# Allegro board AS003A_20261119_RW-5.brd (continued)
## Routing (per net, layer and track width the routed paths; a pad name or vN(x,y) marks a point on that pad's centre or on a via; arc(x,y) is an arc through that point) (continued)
S1_PCIE_TX_P[1]: length 124.5
  L09_DIG w0.079: v3(330.45,278.13) 330.45,277.65 330.56,277.55 338.05,277.55 340.98,274.62 354.17,274.62 356.3,272.49 356.3,259.79 353.74,257.23 319.79,257.23 294.62,232.07 294.62,227.94 294.83,227.73 294.83,227.71
  L09_DIG w0.102: v1(294.43,223.83) 294.83,224.23 294.83,227.71
  BOTTOM w0.117: C259.2 R128.1 arc(330,277.76) 330.26,277.94 v3(330.45,278.13)
S1_PCIE_TX_P[2]: length 124.5
  L09_DIG w0.079: 292.43,227.71 292.43,227.73 292.64,227.94 292.64,233.3 318.47,259.13 342.27,259.13 344.29,261.15 344.29,267.35 342.93,268.71 340.51,268.71 335.39,273.84 326.31,273.84 323.52,276.63 323.52,281.6 322.02,283.11 319.76,283.11 318.56,281.91 318.56,278.18 317.35,276.97 315.31,276.97 315.21,276.87 v3(315.21,276.48)
  L09_DIG w0.102: v1(292.83,223.83) 292.43,224.23 292.43,227.71
  BOTTOM w0.117: C260.2 R132.1 arc(314.76,276.84) 315.02,276.67 v3(315.21,276.48)
S1_PCIE_TX_P[3]: length 124.5
  L09_DIG w0.079: v3(299.97,276.48) 299.97,276.88 300.05,276.96 307.08,276.96 309.69,274.34 311.28,274.34 313.89,271.73 313.89,258.12 312.91,257.14 282.98,257.14 282.04,256.2 282.04,254.08 282.84,253.29 303.53,253.29 305,251.82 305,248.55 291.04,234.59 291.04,227.94 290.83,227.73 290.83,227.71
  L09_DIG w0.102: 290.83,227.71 290.83,224.23 v1(291.23,223.83)
  BOTTOM w0.117: C264.2 R136.1 arc(299.52,276.84) 299.78,276.67 v3(299.97,276.48)
S1_PCIE_TX_P[4]: length 124.5
  L09_DIG w0.079: v3(284.73,276.48) 284.73,276.89 284.81,276.97 289,276.97 289.44,276.53 289.44,267.34 279.11,257.02 254.39,257.02 253.21,255.84 253.21,252.49 254.31,251.39 288.49,251.39 289.44,250.45 289.44,227.94 289.23,227.73 289.23,227.71
  L09_DIG w0.102: v1(289.63,223.83) 289.23,224.23 289.23,227.71
  BOTTOM w0.117: C268.2 R140.1 arc(284.28,276.84) 284.54,276.67 v3(284.73,276.48)
S1_PCIE_TX_P[5]: length 124.5
  L09_DIG w0.079: 287.63,227.71 287.63,227.73 287.84,227.94 287.84,229.77 283.53,234.07 283.53,236.81 277.09,243.26 277.09,245.43 275.42,247.11 243.75,247.11 242.19,248.67 242.19,256.93 244.02,258.76 270.54,258.76 273.33,261.55 273.33,275.69 272.06,276.96 269.57,276.96 269.49,276.88 v3(269.49,276.48)
  L09_DIG w0.102: v1(288.03,223.83) 287.63,224.23 287.63,227.71
  BOTTOM w0.117: C275.2 R144.1 arc(269.04,276.84) 269.3,276.67 v3(269.49,276.48)
S1_PCIE_TX_P[6]: length 124.5
  L09_DIG w0.079: v3(254.25,276.48) 254.25,276.89 254.33,276.97 255.68,276.97 257.89,274.76 257.89,265.2 255.24,262.55 235.76,262.55 231.22,258.01 231.22,249.58 236.82,243.99 273.32,243.99 281.45,235.86 281.45,234.09 286.24,229.3 286.24,227.94 286.03,227.73 286.03,227.71
  L09_DIG w0.102: v1(286.43,223.83) 286.03,224.23 286.03,227.71
  BOTTOM w0.117: v3(254.25,276.48) 254.06,276.67 arc(253.8,276.84) R148.1 C279.2
S1_PCIE_TX_P[7]: length 124.5
  L09_DIG w0.079: v3(239.01,276.48) 239.01,276.88 239.09,276.96 240.94,276.96 243.21,274.7 243.21,265.34 241.9,264.03 227.95,264.03 225.45,261.52 225.45,243.2 226.35,242.3 270.84,242.3 284.64,228.5 284.64,227.94 284.43,227.73 284.43,227.71
  L09_DIG w0.102: 284.43,227.71 284.43,224.23 v1(284.83,223.83)
  BOTTOM w0.117: v3(239.01,276.48) 238.82,276.67 arc(238.56,276.84) R152.1 C280.2
S1_PHY0_RESEXT: length 9.1
  BOTTOM w0.508: v1(298.7,232.83) R109.1
  vias: v1(291.23,221.43)
S1_PHY0_RESEXT_1: length 3
  BOTTOM w0.508: R109.2 K3.3
S1_PHY0_SYS_CLK1R_N:
  vias: v1(330.33,236.21)
S1_PHY0_SYS_CLK1R_P:
  vias: v1(330.33,220.99)
S1_PHY0_SYS_CLK2_N:
  vias: v1(336.16,228.85) v1(337.75,228.85)
S1_PHY0_SYS_CLK2_P:
  vias: v1(336.16,227.58) v1(337.75,227.88)
S1_PHY0_SYS_CLK3_N:
  vias: v1(331.34,235.2) v1(335.16,230.12) v1(335.16,228.85)
S1_PHY0_SYS_CLK3_P:
  vias: v1(331.34,222) v1(335.16,227.58) v1(335.16,226.31)
S1_PHY0_SYS_CLK_N:
  vias: v1(292.83,222.23)
S1_PHY0_SYS_CLK_P:
  vias: v1(292.83,221.43)
S1_PHY1_RESEXT: length 9.1
  BOTTOM w0.508: v1(287.65,232.83) R111.1
  vias: v1(288.03,221.43)
S1_PHY1_RESEXT_1: length 3
  BOTTOM w0.508: R111.2 K4.3
S1_PHY1_SYS_CLK1R_N:
  vias: v1(330.33,253.48)
S1_PHY1_SYS_CLK1R_P:
  vias: v1(330.33,238.26)
S1_PHY1_SYS_CLK2_N:
  vias: v1(336.16,246.13) v1(337.75,246.13)
S1_PHY1_SYS_CLK2_P:
  vias: v1(336.16,244.86) v1(337.75,245.15)
S1_PHY1_SYS_CLK3_N:
  vias: v1(331.34,252.48) v1(335.16,247.4) v1(335.16,246.13)
S1_PHY1_SYS_CLK3_P:
  vias: v1(331.34,239.27) v1(335.16,244.86) v1(335.16,243.59)
S1_PHY1_SYS_CLK_N:
  vias: v1(289.63,222.23)
S1_PHY1_SYS_CLK_P:
  vias: v1(289.63,221.43)
S1_UHC4_1F:
  vias: v1(221.49,237.87) v1(221.49,235.58) v1(221.49,233.3) v1(221.49,231.01)
S1_UHC4_1GS:
  vias: v1(221.49,242.44)
S1_UHC4_1S:
  vias: v1(221.49,240.16)
S1_UHC4_2F:
  vias: v1(380.37,252.73) v1(380.37,250.44) v1(380.37,248.16) v1(380.37,245.87)
S1_UHC4_2GS:
  vias: v1(380.37,257.3)
S1_UHC4_2S:
  vias: v1(380.37,255.02)
S1_UHC4_3F:
  vias: v1(221.62,194.44) v1(221.62,192.15) v1(221.62,189.87) v1(221.62,187.58)
S1_UHC4_3GS:
  vias: v1(221.62,199.01)
S1_UHC4_3S:
  vias: v1(221.62,196.72)
S1_VCC18V_VQPS:
  vias: v1(294.43,207.83)
S1_XIN:
  vias: v1(290.43,203.03)
UDBGND:
  vias: v1(169.98,297.69) v1(169.98,294.89) v1(170.17,137.92) v1(170.45,135.64) v1(190.97,135.07) v1(191.06,137.92) v1(206.67,297.56) v1(206.96,295.27) v1(320.21,132.84) v1(320.49,130.55) v1(344.73,133.6) v1(344.8,130.75) v1(401.5,133.6) v1(401.5,130.56) v1(421.89,277.57) v1(422.27,283.63) v1(425.45,283.23) v1(425.96,277.57)
UT1_UP5V: length 45
  TOP w0.508: RV8.1 296.16,180.12 K7.1 ; RV11.1 352.65,227.08 K10.1 ; LRB3.1 172.72,190.5 KS3.3 ; KS1.1 161.17,161.88 LRB1.1 ; K5.1 256.06,208.53 RV6.1 ; K8.1 328.52,196.85 RV9.1 ; RV13.1 369.92,238.76 K12.1 ; LRB2.1 178.32,161.88 KS2.1 ; K4.1 284.86,249.4 RV5.1 ; LRB4.1 172.72,181.61 KS4.3 ; K6.1 328.52,214.12 RV7.1 ; K9.1 283.97,180.12 RV10.1 ; RV4.1 295.91,249.4 K3.1 ; RV12.1 352.65,244.35 K11.1
  vias: v1(171.87,137.92) v1(172.95,135.64) v1(208.37,297.56) v1(209.46,295.27) v1(321.94,248.07) v1(321.94,230.8) v1(321.91,132.84) v1(322.99,130.55) v1(422.27,285.33) v1(425.45,285.73)
UT1_URW00: length 7.7
  TOP w0.508: LDB3.2 162.56,190.5 KS3.1
UT1_URW01: length 7.7
  TOP w0.508: LDB4.2 162.56,181.61 KS4.1
UT1_URW02: length 3.8
  TOP w0.508: KS2.9 182.36,161.88 LDB2.2
UT1_URW03: length 3.8
  TOP w0.508: LDB1.2 165.21,161.88 KS1.9
N19435169: length 19.6
  BOTTOM w0.508: C287.1 390.66,230.38 391.41,230.38
  BOTTOM w0.762: 391.41,230.38 C285.1 394.55,230.38 395.06,229.87 395.06,228.09 ; R15.1 R153.1 ; R153.1 395.06,225.81 395.06,228.09 ; R153.1 R162.1 ; R16.1 R162.1 ; R162.1 395.06,228.09
N19572213:
  vias: v1(321.94,229.95) v1(321.94,227.83)
N19572313:
  vias: v1(321.94,247.23) v1(321.94,245.1)
N19572428:
  vias: v1(339.16,229.83) v1(340.74,229.35)
N19572509:
  vias: v1(339.16,247.1) v1(340.74,246.63)
N19574075: length 1.2
  TOP w0.508: RV4.2 DV4.1
N19574343: length 1.2
  TOP w0.508: RV5.2 DV5.1
N19575291: length 1.2
  TOP w0.508: RV8.2 DV8.1
N19575453: length 3.5
  BOTTOM w0.508: K7.4 296.17,188.07 OSC1.3
N19585514: length 1.2
  TOP w0.508: RV10.2 DV10.1
N19585599: length 6.7
  BOTTOM w0.508: OSC1.1 287.52,185.53 K9.6 K9.3
N19585804: length 2.6
  BOTTOM w0.508: R116.1 K9.4
N19747460: length 2
  BOTTOM w0.762: R21.1 BD16.2
N19747478: length 8.4
  BOTTOM w0.508: 391.41,252.22 390.66,252.22 C290.1
  BOTTOM w0.762: R22.1 BD15.2 395.06,251.71 394.55,252.22 C288.1 391.41,252.22
N19756616: length 1.2
  TOP w0.508: RV11.2 DV11.1
N19756896:
  vias: v1(342.26,228.35)
N19756906:
  vias: v1(342.26,229.35)
N19757084: length 1.2
  TOP w0.508: RV12.2 DV12.1
N19757142:
  vias: v1(342.26,245.63)
N19757144:
  vias: v1(342.26,246.63)
N19788638: length 1.2
  TOP w0.508: RV9.2 DV9.1
N20007134: length 1.2
  TOP w0.508: RV6.2 DV6.1
N20007610: length 1.2
  TOP w0.508: RV7.2 DV7.1
N20116208:
  vias: v1(350.39,233.75) v1(352.14,233.75)
N20116223:
  vias: v1(348.49,233.75)
N20117866:
  vias: v1(356.23,240.83) v1(358.07,240.86)
N20117958: length 1.2
  TOP w0.508: RV13.2 DV13.1
N20118012:
  vias: v1(359.54,239.78)
N20118014:
  vias: v1(359.54,240.78)
N20118429:
  vias: v1(339.78,234.26)
N20125555:
  vias: v1(339.78,235.53)
N20125558:
  vias: v1(339.78,239.09)
N20322895: length 3.7
  BOTTOM w0.762: KS2.4 KS2-4.1
N20322897: length 1.5
  TOP w0.508: LDB1.1 LRB1.2
N20322901: length 3.6
  BOTTOM w0.762: KS2.3 KS2-3.1
N20322902: length 3.7
  BOTTOM w0.762: KS2.6 KS2-6.1
N20322905: length 3.6
  BOTTOM w0.762: KS2.7 KS2-7.1
N20322907: length 1.5
  TOP w0.508: LDB2.1 LRB2.2
N20322911: length 3.7
  BOTTOM w0.762: KS1.4 KS1-4.1
N20322913: length 3.6
  BOTTOM w0.762: KS1.3 KS1-3.1
N20322914: length 3.7
  BOTTOM w0.762: KS1.6 KS1-6.1
N20322915: length 3.6
  BOTTOM w0.762: KS1.7 KS1-7.1
N20322919: length 3.6
  BOTTOM w0.762: KS1.2 KS1-2.1
N20322920: length 3.6
  BOTTOM w0.762: KS1.8 KS1-8.1
N20322921: length 3.6
  BOTTOM w0.762: KS2.2 KS2-2.1
N20322922: length 3.6
  BOTTOM w0.762: KS2.8 KS2-8.1
N20322925: length 1.5
  TOP w0.508: LRB3.2 LDB3.1
N20322930: length 1.5
  TOP w0.508: LRB4.2 LDB4.1
N20322942: length 3.8
  TOP w0.762: KS4.4 180.85,179.07 KS4-4.1
N20322943: length 3.8
  TOP w0.762: KS4.5 180.85,176.53 KS4-5.1
N20322944: length 3.6
  TOP w0.762: KS4.8 KS4-8.1
N20322953: length 3.6
  TOP w0.762: KS3.8 KS3-8.1
N20322954: length 3.8
  TOP w0.762: KS3.4 180.85,187.96 KS3-4.1
N20322955: length 3.8
  TOP w0.762: KS3-5.1 180.85,185.42 KS3.5
N20403651:
  vias: v1(55.49,220.9) v1(55.48,219.88)
N20403655: length 9.7
  BOTTOM w0.117: OSC5.1 58.98,218.17 R259.1 61.98,220.26 64.06,220.26 K13.6
N20403856: length 4.6
  TOP w0.254: K13.8 DV14.2 S1_K13_CBIT.1
N20403862: length 1.3
  TOP w0.254: DV14.1 RV14.2
N20403864: length 48.1
  TOP w0.508: K13.1 71.34,215.18 RV14.1 73.08,213.53 ; v1(41.28,220.4) 39.75,218.87 RV16.1
  L03_DIG w1.016: v1(41.28,220.4) 42.42,221.53 45.21,221.53 45.85,222.17 54.74,222.17 55.63,223.06 v1(65.66,223.06) 70.61,223.06 72.52,221.15 72.52,217.22 K13.1
  BOTTOM w0.508: K15.1 v1(41.28,220.4)
N20403912: length 3.1
  BOTTOM w0.117: K13.4 62.21,216.71 R261.1
N20403914: length 3.1
  BOTTOM w0.117: R261.2 62.21,217.72 K13.5
N20408352: length 7.7
  TOP w0.254: DV16.2 39.75,214.55 v1(41.28,213.01) 40,211.74 S1_K15_CBIT.1
  BOTTOM w0.254: K15.9 v1(41.28,213.01)
N20408383: length 1.2
  TOP w0.254: DV16.1 RV16.2
N20409909:
  vias: v1(55.49,203.75) v1(55.48,202.74)
N20409913: length 9.7
  BOTTOM w0.117: OSC6.1 58.98,201.02 R260.1 61.98,203.12 64.06,203.12 K14.6
N20410006: length 4.6
  TOP w0.254: K14.8 DV15.2 S1_K14_CBIT.1
N20410012: length 1.3
  TOP w0.254: DV15.1 RV15.2
N20410014: length 48.1
  TOP w0.508: v1(41.28,203.26) 39.75,201.72 RV17.1 ; 73.08,196.39 RV15.1 71.34,198.04 K14.1
  L03_DIG w1.016: K14.1 72.52,200.08 72.52,204.01 70.61,205.91 55.63,205.91 54.74,205.02 45.85,205.02 45.21,204.39 42.42,204.39 v1(41.28,203.26)
  BOTTOM w0.508: K16.1 v1(41.28,203.26)
N20410038: length 3.1
  BOTTOM w0.117: R262.1 62.21,199.57 K14.4
N20410040: length 3.1
  BOTTOM w0.117: K14.5 62.21,200.57 R262.2
N20410345: length 3.4
  TOP w0.508: S1_DB_OSC5_PWR.1 v1(58.76,221.41) v1(58.76,219.75)
N20410600: length 4.9
  TOP w0.254: v1(41.28,195.87) 39.75,197.4 DV17.2
  BOTTOM w0.254: K16.9 v1(41.28,195.87)
N20410614: length 1.2
  TOP w0.254: DV17.1 RV17.2
N20412222: length 1.7
  TOP w0.762: v1(58.76,202.61) v1(58.76,204.26)
N20412556: length 2.3
  BOTTOM w0.117: K15.6 v1(51.43,213.02)
N20412563: length 2.3
  BOTTOM w0.117: K15.4 v1(51.43,220.39)
N20412610: length 2.3
  BOTTOM w0.117: K16.6 v1(51.43,195.88)
N20412613: length 2.3
  BOTTOM w0.117: K16.4 v1(51.43,203.24)
N20439603:
  vias: v1(55.49,162.94) v1(55.48,161.93)
N20439607: length 9.7
  BOTTOM w0.117: OSC7.1 58.98,160.21 R273.1 61.98,162.31 64.06,162.31 K17.6
N20439693: length 4.6
  TOP w0.254: K17.8 DV18.2 S1_K17_CBIT.1
N20439699: length 1.3
  TOP w0.254: DV18.1 RV18.2
N20439701: length 48.1
  TOP w0.508: K17.1 71.34,157.23 RV18.1 73.08,155.57 ; RV19.1 39.75,160.91 v1(41.28,162.44)
  L03_DIG w1.016: K17.1 72.52,159.27 72.52,163.19 70.61,165.1 55.63,165.1 54.74,164.21 45.85,164.21 45.21,163.58 42.42,163.58 v1(41.28,162.44)
  BOTTOM w0.508: K18.1 v1(41.28,162.44)
N20439733: length 3.1
  BOTTOM w0.117: K17.4 62.21,158.76 R274.1
N20439735: length 3.1
  BOTTOM w0.117: K17.5 62.21,159.76 R274.2
N20439828: length 4.9
  TOP w0.254: v1(41.28,155.06) 39.75,156.59 DV19.2
  BOTTOM w0.254: K18.9 v1(41.28,155.06)
N20439842: length 1.2
  TOP w0.254: DV19.1 RV19.2
N20439950:
  vias: v1(55.49,180.09) v1(55.48,179.07)
N20439954: length 9.7
  BOTTOM w0.117: K19.6 64.06,179.45 61.98,179.45 R281.1 58.98,177.36 OSC8.1
N20440050: length 4.6
  TOP w0.254: S1_K19_CBIT.1 DV20.2 K19.8
N20440056: length 1.3
  TOP w0.254: DV20.1 RV20.2
N20440058: length 48.1
  TOP w0.508: RV21.1 39.75,178.06 v1(41.28,179.59) ; 73.08,172.72 RV20.1 71.34,174.37 K19.1
  L03_DIG w1.016: v1(41.28,179.59) 42.42,180.72 45.21,180.72 45.85,181.36 54.74,181.36 55.63,182.25 70.61,182.25 72.52,180.34 72.52,176.41 K19.1
  BOTTOM w0.508: K20.1 v1(41.28,179.59)
N20440074: length 3.1
  BOTTOM w0.117: R282.1 62.21,175.9 K19.4
N20440076: length 3.1
  BOTTOM w0.117: R282.2 62.21,176.9 K19.5
N20440163: length 1.7
  TOP w0.762: v1(58.76,161.8) v1(58.76,163.45)
N20440184: length 4.9
  TOP w0.254: DV21.2 39.75,173.73 v1(41.28,172.2)
  BOTTOM w0.254: K20.9 v1(41.28,172.2)
N20440198: length 1.2
  TOP w0.254: DV21.1 RV21.2
N20440326: length 1.7
  TOP w0.762: v1(58.76,178.94) v1(58.76,180.59)
N20440363: length 2.3
  BOTTOM w0.117: K18.6 v1(51.43,155.07)
N20440379: length 2.3
  BOTTOM w0.117: K18.4 v1(51.43,162.43)
N20440395: length 2.3
  BOTTOM w0.117: K20.6 v1(51.43,172.21)
N20440397: length 2.3
  BOTTOM w0.117: K20.4 v1(51.43,179.58)

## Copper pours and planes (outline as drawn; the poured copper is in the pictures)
DGND on L34_DIG (solid shape): 304.47,199.71 304.47,197.53 305.73,196.28 305.75,196.18 305.68,196.11 305.62,196.08 305.53,196.09 305.48,196.18 305.48,196.38 304.33,197.53 304.33,199.66 303.16,200.83 303.15,200.88 303.19,200.91 303.27,200.91
DGND on L34_DIG (solid shape): 316.84,206.07 316.86,205.96 316.77,205.9 316.66,205.9 312.01,210.55 310.42,210.55 310.34,210.59 310.33,210.68 310.35,210.81 310.33,210.94 310.35,211.03 310.43,211.07 311.84,211.07
DGND on L34_DIG (solid shape): 316.85,209.27 316.85,208.43 316.79,208.34 316.68,208.36 312.67,212.38 310.44,212.38 310.36,212.42 310.34,212.5 310.34,212.65 310.31,212.78 310.31,212.88 310.4,212.93 313.2,212.93
DGND on L34_DIG (solid shape): 271.92,221.8 272.01,221.77 272.05,221.72 272.05,220.75 272.01,220.66 271.92,220.65 271.32,220.12 272.09,219.89 272.13,219.91 272.16,219.89 272.49,219.56 272.52,219.45 272.42,219.39 271.68,219.39 271.21,219.86 271.21,221.46 271.25,221.54 271.34,221.55 271.63,221.57 271.85,221.75
DGND on L34_DIG (solid shape): 267.6,209.81 267.63,209.86 267.69,209.85 269.2,208.34 276.71,208.34 276.8,208.27 276.78,208.16 276.07,207.45 275.68,207.45 275.6,207.49 275.59,207.59 275.17,208.23 274.75,207.59 274.74,207.49 274.66,207.45 272.28,207.45 272.2,207.49 272.19,207.59 271.77,208.23 271.35,207.59 271.34,207.49 271.26,207.45 269.9,207.45 267.6,209.75
DGND on L34_DIG (solid shape): outline of 231 points within 256.01,222.42 272.51,227.99
DGND on L34_DIG (solid shape): 290.31,177.44 290.37,177.53 290.48,177.51 292.1,175.89 292.1,172.91 312.43,152.57 312.43,113.48 315.89,110.02 315.89,99.5 315.82,99.4 315.7,99.45 314.12,99.06 315.7,98.67 315.82,98.72 315.89,98.62 315.89,89.34 315.82,89.24 315.7,89.29 314.12,88.9 315.7,88.51 315.82,88.56 315.89,88.46 315.89,79.18 315.82,79.08 315.7,79.13 314.12,78.74 315.7,78.35 315.82,78.4 315.89,78.3 315.89,69.02 315.82,68.92 315.7,68.97 314.12,68.58 315.7,68.19 315.82,68.24 315.89,68.14 315.89,58.86 315.82,58.76 315.7,58.81 314.12,58.42 315.7,58.03 315.82,58.08 315.89,57.98 315.89,48.7 315.82,48.6 315.7,48.65 314.12,48.26 315.7,47.87 315.82,47.92 315.89,47.82 315.89,38.54 315.82,38.44 315.7,38.49 315.28,38.88 314.7,38.9 314.68,38.89 314,39.57 314,109.16 312.16,111 312.16,151.93 290.31,173.78 290.31,175.38 290.37,175.47 290.49,175.45 291.29,175.75 290.49,176.05 290.37,176.02 290.31,176.12
DGND on L34_DIG (solid shape): outline of 84 points within 319.75,38.59 409.78,212.05
DGND on L34_DIG (solid shape): outline of 650 points within 310.33,38.47 404.77,214.59
DGND on L34_DIG (solid shape): outline of 764 points within 295.16,97.06 323.36,192.8
DGND on L34_DIG (solid shape): outline of 844 points within 239.23,38.5 268.13,209.44
DGND on L34_DIG (solid shape): outline of 1276 points within 295.59,38.47 326.04,200.8
DGND on L02_DGND: 302.07,1.02 290.83,6.67 279.59,1.02 1.02,1.02 1.02,428.24 205.93,428.24 217.17,422.59 228.41,428.24 353.25,428.24 364.49,422.59 375.73,428.24 580.64,428.24 580.64,1.02 ; 1 cut-out
DGND on L03_DIG, L05_DIG, L07_DIG, L09_DIG, L30_DIG: 1.27,1.27 1.27,427.99 205.8,427.99 217.17,422.33 228.54,427.99 353.12,427.99 364.49,422.33 375.86,427.99 435.88,427.99 435.88,1.27 302.2,1.27 290.83,6.93 279.46,1.27
(no net) on BOTTOM: 254.28,149.15 254.28,152.35 253.67,152.96 244.53,152.96 243.81,152.25 243.81,149.15 243.97,149 254.13,149
(no net) on BOTTOM: 364.77,164.52 364.77,165.84 365.68,166.75 365.68,169.11 364.9,169.9 356.08,169.9 355.4,169.21 355.4,166.73 356.59,165.53 356.59,164.44 356.67,164.36 364.62,164.36
(no net) on BOTTOM: 55.24,160.15 55.24,163.58 55.63,163.96 57.53,163.96 57.53,161.16 57.28,160.91 56.9,160.91 56.77,160.78 56.77,159.89 55.5,159.89
(no net) on BOTTOM: 393.19,226.31 392.56,226.95 390.65,226.95 389.76,227.84 389.76,233.25 391.31,234.8 395.61,234.8 396.09,234.31 397.59,234.31 397.59,236.91 396.62,237.87 388.49,237.87 385.95,235.33 385.95,219.2 388.62,216.53 397.13,216.53 397.61,217.02 397.61,219.63 394.92,219.63 393.19,221.36
(no net) on BOTTOM: 323.37,149.15 323.37,150.47 324.28,151.38 324.28,153.75 323.49,154.53 314.68,154.53 313.99,153.85 313.99,151.36 315.19,150.16 315.19,149.07 315.26,149 323.21,149
(no net) on BOTTOM: 324.13,164.52 324.13,165.84 325.04,166.75 325.04,169.11 324.26,169.9 315.44,169.9 314.76,169.21 314.76,166.73 315.95,165.53 315.95,164.44 316.03,164.36 323.98,164.36
(no net) on BOTTOM: 55.24,177.29 55.24,180.72 55.63,181.1 57.53,181.1 57.53,178.31 57.28,178.05 56.9,178.05 56.77,177.93 56.77,177.04 55.5,177.04
(no net) on BOTTOM: 378.54,186.46 375.34,186.46 374.74,185.87 374.74,178.9 375.36,178.28 378.61,178.28 378.69,178.36 378.69,186.31
(no net) on BOTTOM: 55.24,218.1 55.24,221.53 55.63,221.91 57.53,221.91 57.53,219.12 57.28,218.87 56.9,218.87 56.77,218.74 56.77,217.85 55.5,217.85
(no net) on BOTTOM: 343.81,164.52 343.81,165.84 344.73,166.75 344.73,169.11 343.94,169.9 335.13,169.9 334.44,169.21 334.44,166.73 335.64,165.53 335.64,164.44 335.71,164.36 343.66,164.36
(no net) on BOTTOM: 289.84,149.15 289.84,153.26 288.57,154.53 282.68,154.53 281.66,153.52 281.66,149.07 281.74,149 289.69,149
(no net) on BOTTOM: 270.28,154.53 261.09,154.53 259.31,152.76 259.31,149.25 259.56,149 272.06,149 272.16,149.1 272.16,152.65
(no net) on BOTTOM: 306.35,149.15 306.35,150.47 307.26,151.38 307.26,153.75 306.48,154.53 297.66,154.53 296.98,153.85 296.98,151.36 298.17,150.16 298.17,149.07 298.25,149 306.2,149
(no net) on BOTTOM: 55.24,200.96 55.24,204.39 55.63,204.77 57.53,204.77 57.53,201.97 57.28,201.72 56.9,201.72 56.77,201.59 56.77,200.7 55.5,200.7
(no net) on BOTTOM: 375.59,194.79 378.61,194.79 378.69,194.87 378.69,200.66 378.66,200.69 375.39,200.69 374.98,200.28 374.98,195.4
(no net) on L02_DGND: 59.94,494.67 95,494.67 95.5,495.17 95.5,511.05 95,511.56 59.94,511.56 59.44,511.05 59.44,495.17
(no net) on L02_DGND: 60.58,476.76 95.63,476.76 96.14,477.27 96.14,493.14 95.63,493.65 60.58,493.65 60.07,493.14 60.07,477.27
(no net) on L32_DIG, L34_DIG: 1.27,1.27 1.27,427.99 205.8,427.99 217.17,422.33 228.54,427.99 353.12,427.99 364.49,422.33 375.86,427.99 435.88,427.99 435.88,1.27 302.2,1.27 290.83,6.93 279.46,1.27
S1_DPS1 on BOTTOM (solid shape): 307.26,153.75 307.26,151.38 306.35,150.47 306.35,149.15 306.2,149 298.25,149 298.17,149.07 298.17,150.16 296.98,151.36 296.98,153.85 297.66,154.53 306.48,154.53
S1_DPS3 on BOTTOM (solid shape): 378.69,186.31 378.69,178.36 378.61,178.28 375.36,178.28 374.74,178.9 374.74,185.87 375.34,186.46 378.54,186.46
S1_DPS4 on BOTTOM (solid shape): 325.04,169.11 325.04,166.75 324.13,165.84 324.13,164.52 323.98,164.36 316.03,164.36 315.95,164.44 315.95,165.53 314.76,166.73 314.76,169.21 315.44,169.9 324.26,169.9
S1_DPS5 on BOTTOM (solid shape): 289.84,153.26 289.84,149.15 289.69,149 281.74,149 281.66,149.07 281.66,153.52 282.68,154.53 288.57,154.53
S1_DPS7 on BOTTOM (solid shape): 324.28,153.75 324.28,151.38 323.37,150.47 323.37,149.15 323.21,149 315.26,149 315.19,149.07 315.19,150.16 313.99,151.36 313.99,153.85 314.68,154.53 323.49,154.53
S1_DPS9 on BOTTOM (solid shape): 365.68,169.11 365.68,166.75 364.77,165.84 364.77,164.52 364.62,164.36 356.67,164.36 356.59,164.44 356.59,165.53 355.4,166.73 355.4,169.21 356.08,169.9 364.9,169.9
S1_DPS10 on BOTTOM (solid shape): 344.73,169.11 344.73,166.75 343.81,165.84 343.81,164.52 343.66,164.36 335.71,164.36 335.64,164.44 335.64,165.53 334.44,166.73 334.44,169.21 335.13,169.9 343.94,169.9
S1_DPS11 on BOTTOM: 375.59,206.48 378.61,206.48 378.69,206.55 378.69,212.34 378.66,212.37 375.39,212.37 374.98,211.96 374.98,207.09
S1_DPS12 on BOTTOM: 375.59,164.82 378.61,164.82 378.69,164.9 378.69,170.69 378.66,170.71 375.39,170.71 374.98,170.31 374.98,165.43
S1_DPS17 on BOTTOM (solid shape): 397.59,236.91 397.59,234.31 396.09,234.31 395.61,234.8 391.31,234.8 389.76,233.25 389.76,227.84 390.65,226.95 392.56,226.95 393.19,226.31 393.19,221.36 394.92,219.63 397.61,219.63 397.61,217.02 397.13,216.53 388.62,216.53 385.95,219.2 385.95,234.85 386.92,234.85 386.92,234.79 386.93,234.73 386.94,234.68 386.97,234.62 387,234.57 387.03,234.53 387.08,234.49 387.13,234.45 387.18,234.43 387.23,234.41 387.29,234.39 387.35,234.39 387.41,234.39 387.47,234.41 387.52,234.43 387.57,234.45 387.62,234.49 387.67,234.53 387.7,234.57 387.73,234.62 387.76,234.68 387.77,234.73 387.78,234.79 387.78,234.85 387.77,234.91 387.76,234.97 387.73,235.02 387.7,235.07 387.67,235.12 387.62,235.16 387.57,235.19 387.52,235.22 387.47,235.24 387.41,235.25 387.35,235.26 387.29,235.25 387.23,235.24 387.18,235.22 387.13,235.19 387.08,235.16 387.03,235.12 387,235.07 386.97,235.02 386.94,234.97 386.93,234.91 386.92,234.85 385.95,234.85 385.95,235.33 388.49,237.87 396.62,237.87
S1_DPS20 on BOTTOM: 397.64,243.71 394.08,243.71 393.7,244.09 393.7,250.32 390.27,250.32 389.38,251.21 389.38,256.03 390.4,257.05 395.1,257.05 395.86,256.29 395.86,254 396.11,253.75 397.51,253.75 397.51,258.83 396.24,260.1 387.86,260.1 385.7,257.94 385.7,242.44 388.24,239.9 397,239.9 397.64,240.54
S1_DPS23 on BOTTOM (solid shape): 272.16,152.65 272.16,149.1 272.06,149 259.56,149 259.31,149.25 259.31,152.76 261.09,154.53 270.28,154.53
S1_DPS27 on BOTTOM (solid shape): 254.28,152.35 254.28,149.15 254.13,149 243.97,149 243.81,149.15 243.81,152.25 244.53,152.96 253.67,152.96
S1_DPS31 on BOTTOM (solid shape): 378.69,200.66 378.69,194.87 378.61,194.79 375.59,194.79 374.98,195.4 374.98,200.28 375.39,200.69 378.66,200.69
S1_OSC5_6_GND on L02_DGND: 37.85,191.18 74.29,191.18 74.93,191.81 74.93,224.45 74.42,224.96 37.85,224.96 37.34,224.45 37.34,191.69
S1_OSC7_8_GND on L02_DGND (solid shape): 95.5,511.05 95.5,495.17 95,494.67 59.94,494.67 59.44,495.17 59.44,511.05 59.94,511.56 95,511.56
S1_OSC7_8_GND on L02_DGND (solid shape): 96.14,493.14 96.14,477.27 95.63,476.76 60.58,476.76 60.07,477.27 60.07,493.14 60.58,493.65 95.63,493.65
S1_OSC7_8_GND on L02_DGND: 37.85,150.37 74.29,150.37 74.93,151 74.93,183.64 74.42,184.15 37.85,184.15 37.34,183.64 37.34,150.88
N19435169 on BOTTOM: 397.59,230.99 397.59,222.96 397.51,222.88 394.33,222.88 393.95,223.27 393.95,226.44 392.94,227.46 390.78,227.46 390.37,227.86 390.37,230.61 390.45,230.68 391.26,230.68 391.57,230.99
N20403651 on BOTTOM (solid shape): 57.53,219.12 57.28,218.87 56.9,218.87 56.77,218.74 56.77,217.85 55.5,217.85 55.24,218.1 55.24,219.67 55.25,219.68 55.29,219.88 55.25,220.09 55.24,220.1 55.24,221.53 55.63,221.91 57.53,221.91
N20403651 on L03_DIG: 55.75,213.53 66.17,213.53 66.67,214.04 66.67,220.64 66.17,221.15 55.63,221.15 54.99,220.52 54.99,214.29
N20409909 on BOTTOM (solid shape): 57.53,201.97 57.28,201.72 56.9,201.72 56.77,201.59 56.77,200.7 55.5,200.7 55.24,200.96 55.24,202.52 55.25,202.53 55.29,202.74 55.25,202.94 55.24,202.95 55.24,204.39 55.63,204.77 57.53,204.77
N20409909 on L03_DIG: 55.75,196.39 66.17,196.39 66.67,196.89 66.67,203.5 66.17,204.01 55.63,204.01 54.99,203.37 54.99,197.15
N20439603 on BOTTOM (solid shape): 57.53,161.16 57.28,160.91 56.9,160.91 56.77,160.78 56.77,159.89 55.5,159.89 55.24,160.15 55.24,161.71 55.25,161.72 55.29,161.93 55.25,162.13 55.24,162.14 55.24,163.58 55.63,163.96 57.53,163.96
N20439603 on L03_DIG: 55.75,155.57 66.17,155.57 66.67,156.08 66.67,162.69 66.17,163.19 55.63,163.19 54.99,162.56 54.99,156.34
N20439950 on BOTTOM (solid shape): 57.53,178.31 57.28,178.05 56.9,178.05 56.77,177.93 56.77,177.04 55.5,177.04 55.24,177.29 55.24,178.86 55.25,178.87 55.29,179.07 55.25,179.27 55.24,179.28 55.24,180.72 55.63,181.1 57.53,181.1
N20439950 on L03_DIG: 55.75,172.72 66.17,172.72 66.67,173.23 66.67,179.83 66.17,180.34 55.63,180.34 54.99,179.7 54.99,173.48

Small or netless copper shapes (teardrops, artwork), in the pictures only: 86 on L34_DIG

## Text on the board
User.Comments: CR_UNNAMED_2 | CR_DECAP_33 | CR_DECAP_34 | CR_DECAP_39 | CR_DECAP_41 | CR_DECAP_45 | CR_DECAP_47 | CR_DECAP_50 | CR_DECAP_96 | CR_DECAP_107 | CR_DECAP_53 | CR_DECAP_64 | CR_DECAP_70 | CR_DECAP_81 | CR_DECAP_86 | CR_DECAP_97 | CR_DECAP_54 | CR_DECAP_63 | CR_DECAP_69 | CR_DECAP_74 | CR_DECAP_82 | CR_DECAP_93 | CR_DECAP_106 | CR_DECAP_100 | CR_DECAP_57 | CR_DECAP_65 | CR_DECAP_71 | CR_DECAP_80 | CR_DECAP_87 | CR_DECAP_98 | CR_DECAP_55 | CR_DECAP_62 | CR_DECAP_75 | CR_DECAP_83 | CR_DECAP_92 | CR_DECAP_105 | CR_DECAP_101 | CR_DECAP_58 | CR_DECAP_72 | CR_DECAP_79 | CR_DECAP_88 | CR_DECAP_99 | CR_DECAP_56 | CR_DECAP_61 | CR_DECAP_68 | CR_DECAP_76 | CR_DECAP_84 | CR_DECAP_91 | CR_DECAP_104 | CR_DECAP_95 | CR_DECAP_59 | CR_DECAP_66 | CR_DECAP_73 | CR_DECAP_78 | CR_DECAP_89 | CR_DECAP_102 | CR_DECAP_94 | CR_DECAP_60 | CR_DECAP_67 | CR_DECAP_77 | CR_DECAP_85 | CR_DECAP_90 | CR_DECAP_108 | CR_DECAP_109 | CR_DECAP_110 | CR_DECAP_111 | CR_DECAP_112 | CR_DECAP_113 | CR_DECAP_25 | CR_DECAP_23 | CR_DECAP_21 | CR_DECAP_19 | CR_DECAP_17 | CR_DECAP_15 | CR_DECAP_1 | CR_DECAP_3 | CR_DECAP_4 | CR_DECAP_5 | CR_DECAP_6 | CR_DECAP_7 | CR_DECAP_8 | CR_DECAP_9 | CR_DECAP_10 | CR_DECAP_11 | CR_DECAP_12 | CR_DECAP_103 | CR_RF_2 | CR_S_1 | CR_BULK_CAP_3 | CR_BULK_CAP1_2 | CR_UHC_3 | CR_UHC_2 | CR_BULK_CAP_12 | CR_DECAP_28 | CR_DECAP_30 | CR_DECAP_32 | CR_DECAP_37 | CR_DECAP_36 | CR_DECAP_40 | CR_DECAP_42 | CR_DECAP_44 | CR_DECAP_48 | CR_DECAP_27 | CR_DECAP_29 | CR_DECAP_31 | CR_DECAP_38 | CR_DECAP_35 | CR_DECAP_52 | CR_DECAP_43 | CR_DECAP_46 | CR_DECAP_49 | CR_DECAP_51 | CR_DECAP_2 | CR_DECAP_26 | CR_DECAP_24 | CR_DECAP_22 | CR_DECAP_20 | CR_DECAP_18 | CR_DECAP_16 | CR_DECAP_14 | CR_DECAP_13
DISPLAY_BOTTOM: (0,0) | IN4-40 X 4 | 1.61mm+0.04-0 X 4 | GROUP 7 | GROUP 4 | GROUP 8 | GROUP 3 | GROUP 2 | GROUP 1 | UNIT:MM | PCB Thickness:5.08mm
User.45: 1.65 mm | 8.80 mm | 3.10 mm | 1.75 mm | 1.40 mm | 2.20 mm | 8.6 mm | 1.30 mm | 8.86 mm | 8.2 mm | 1.52 mm | 1.10 mm | 0.75 mm | 13.70 mm | 3.50 mm | 11.38mm | 11.58 mm | GROUP 7 | GROUP 4 | GROUP 8 | GROUP 3 | GROUP 2 | GROUP 1
